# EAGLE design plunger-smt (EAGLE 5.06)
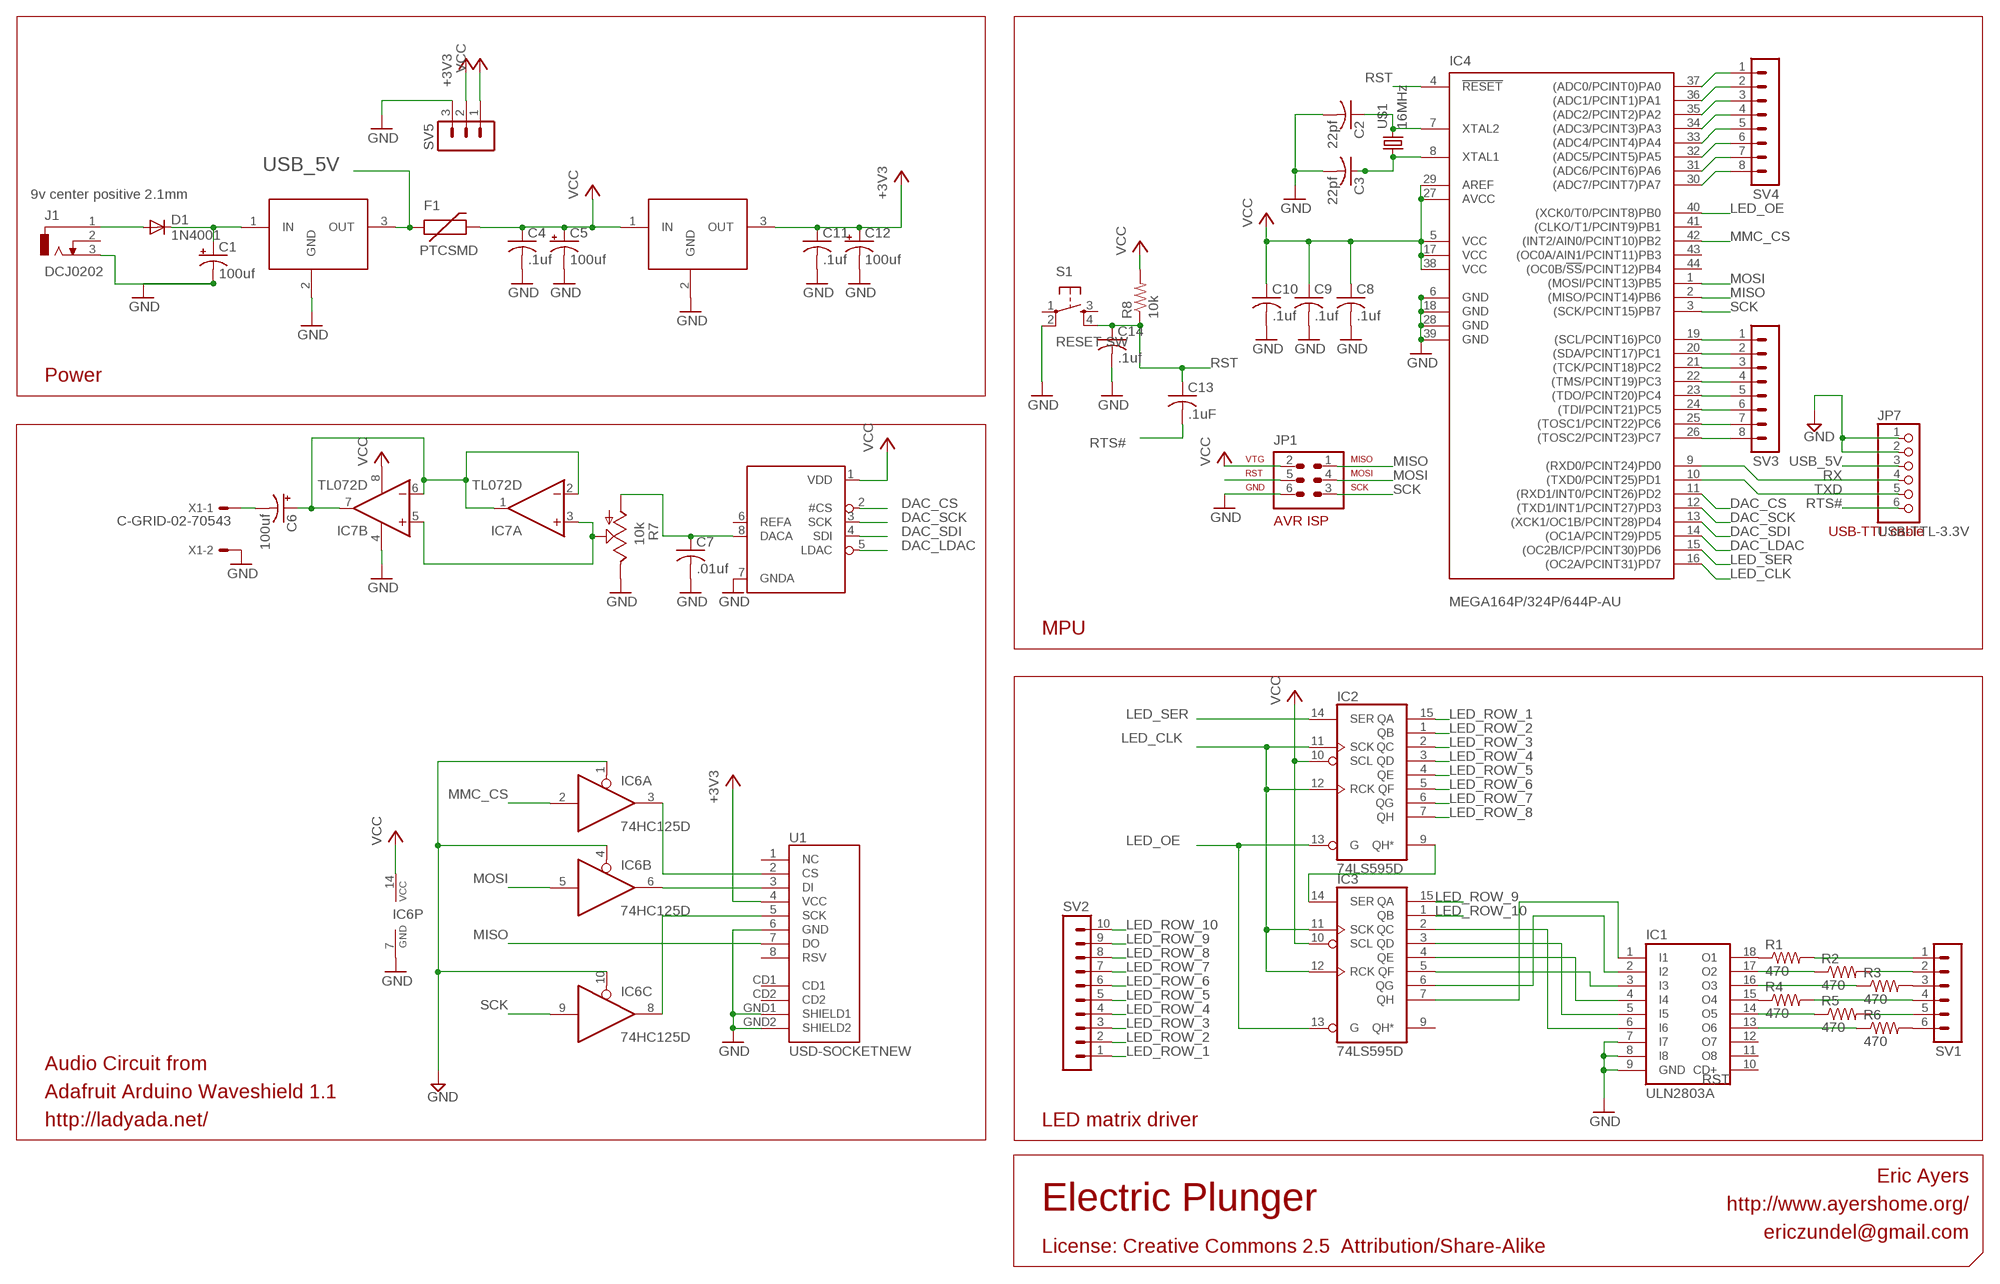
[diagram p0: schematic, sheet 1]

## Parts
C1  100uf  CPOL-USE  [PANASONIC_E]
C2  22pf  C-USC0805  [C0805]
C3  22pf  C-USC0805  [C0805]
C4  .1uf  C-USC0805  [C0805]
C5  100uf  CPOL-USE  [PANASONIC_E]
C6  100uf  CPOL-USD  [PANASONIC_D]
C7  .01uf  C-USC0805  [C0805]
C8  .1uf  C-USC0805  [C0805]
C9  .1uf  C-USC0805  [C0805]
C10  .1uf  C-USC0805  [C0805]
C11  .1uf  C-USC0805  [C0805]
C12  100uf  CPOL-USE  [PANASONIC_E]
C13  .1uF  C-USC0805  [C0805]
C14  .1uf  C-USC0805  [C0805]
D1  1N4001  DIODEPTH  [DIODE-1N4001]
F1  PTCSMD  [PTC-1206]
IC1  ULN2803A  ULN2803AULN2803ADW  [SO18W]
IC2  74LS595D  [SO16]
IC3  74LS595D  [SO16]
IC4  MEGA164P/324P/644P-AU  [TQFP44]
IC6  74HC125D  [SO14]
IC7  TL072D  [SO08]
J1  DCJ0202  [DCJ0202]
JP1  AVR-ISP-6  [AVR-ISP-6]
JP7  USB-TTL-3.3V  PINHD-1X6CLEAN  [1X06-CLEAN]
R1  470  R-US_R0805  [R0805]
R2  470  R-US_R0805  [R0805]
R3  470  R-US_R0805  [R0805]
R4  470  R-US_R0805  [R0805]
R5  470  R-US_R0805  [R0805]
R6  470  R-US_R0805  [R0805]
R7  10k  TRIM_US-S63S  [S63S]
R8  10k  R-US_R0805  [R0805@1]
REG3.3  KFBDT  [DPACK]
REG5.5  KFBDT  [DPACK]
S1  RESET SW  TAC_SWITCHPTH  [TACTILE-PTH]
SV1  MA06-1  [MA06-1]
SV2  MA10-1  [MA10-1]
SV3  MA08-1  [MA08-1]
SV4  MA08-1  [MA08-1]
SV5  MA03-1  [MA03-1]
U1  USD-SOCKETNEW  [MICRO-SD-SOCKET-PP]
U$1  16MHz  CRYTALTC26H  [TC26H]
U$2  MCP4921  [SO8]
X1  C-GRID-02-70543  [70543-02]

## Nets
+3V3: C11.1 C12.+ REG3.3.3(OUT) SV5.2 U1.4(VCC)
DAC_CS: IC4.11((RXD1/INT0/PCINT26)PD2) U$2.2(#CS)
DAC_LDAC: IC4.14((OC1A/PCINT29)PD5) U$2.5(LDAC)
DAC_SCK: IC4.12((TXD1/INT1/PCINT27)PD3) U$2.3(SCK)
DAC_SDI: IC4.13((XCK1/OC1B/PCINT28)PD4) U$2.4(SDI)
GND: C1.- C2.2 C3.2 C4.2 C5.- C7.2 C8.2 C9.2 C10.2 C11.2 C12.- C14.2 IC1.7(I7) IC1.8(I8) IC1.9(GND) IC4.6(GND) IC4.18(GND) IC4.28(GND) IC4.39(GND) IC6.1(A:OE) IC6.4(B:OE) IC6.7(P:GND) IC6.10(C:OE) IC7.4(P:V-) J1.3 JP1.6 JP7.1 JP7.2 R7.E REG3.3.2(GND) REG5.5.2(GND) S1.2 SV5.3 U1.6(GND) U1.GND1(SHIELD1) U1.GND2(SHIELD2) U$2.7(GNDA) X1.2
LED_CLK: IC2.11(SCK) IC2.12(RCK) IC3.11(SCK) IC3.12(RCK) IC4.16((OC2A/PCINT31)PD7)
LED_COL_1: R1.2 SV1.1
LED_COL_3: R3.2 SV1.3
LED_COL_4: R4.2 SV1.4
LED_COL_5: R5.2 SV1.5
LED_COL_6: R6.2 SV1.6
LED_OE: IC2.13(G) IC3.13(G) IC4.40((XCK0/T0/PCINT8)PB0)
LED_ROW_1: IC2.15(QA) SV2.1
LED_ROW_2: IC2.1(QB) SV2.2
LED_ROW_3: IC2.2(QC) SV2.3
LED_ROW_4: IC2.3(QD) SV2.4
LED_ROW_5: IC2.4(QE) SV2.5
LED_ROW_6: IC2.5(QF) SV2.6
LED_ROW_7: IC2.6(QG) SV2.7
LED_ROW_8: IC2.7(QH) SV2.8
LED_ROW_9: IC3.15(QA) SV2.9
LED_ROW_10: IC3.1(QB) SV2.10
LED_SER: IC2.14(SER) IC4.15((OC2B/ICP/PCINT30)PD6)
MISO: IC4.2((MISO/PCINT14)PB6) JP1.1 U1.7(DO)
MMC_CS: IC4.42((INT2/AIN0/PCINT10)PB2) IC6.2(A:I)
MOSI: IC4.1((MOSI/PCINT13)PB5) IC6.5(B:I) JP1.4
N$2: IC1.6(I6) IC3.2(QC)
N$3: IC1.5(I5) IC3.3(QD)
N$4: IC1.4(I4) IC3.4(QE)
N$5: IC1.3(I3) IC3.5(QF)
N$6: IC1.2(I2) IC3.6(QG)
N$8: R2.2 SV1.2
N$10: IC1.13(O6) R6.1
N$11: IC1.18(O1) R1.1
N$12: IC1.16(O3) R3.1
N$13: IC1.14(O5) R5.1
N$14: IC1.1(I1) IC3.7(QH)
N$18: IC1.15(O4) R4.1
N$20: IC1.17(O2) R2.1
N$21: IC4.37((ADC0/PCINT0)PA0) SV4.1
N$23: IC2.9(QH*) IC3.14(SER)
N$24: C2.1 IC4.7(XTAL2) U$1.2
N$25: C3.1 IC4.8(XTAL1) U$1.1
N$30: IC4.36((ADC1/PCINT1)PA1) SV4.2
N$34: C1.+ D1.C REG5.5.1(IN)
N$35: IC6.6(B:O) U1.3(DI)
N$36: IC6.3(A:O) U1.2(CS)
N$37: C6.+ IC7.1(A:OUT) IC7.2(A:-IN) IC7.6(B:-IN) IC7.7(B:OUT)
N$38: IC7.3(A:+IN) IC7.5(B:+IN) R7.S
N$39: C6.- X1.1
N$40: IC4.35((ADC2/PCINT2)PA2) SV4.3
N$41: IC6.8(C:O) U1.5(SCK)
N$42: C7.1 R7.A U$2.8(DACA)
N$43: IC4.34((ADC3/PCINT3)PA3) SV4.4
N$44: IC4.33((ADC4/PCINT4)PA4) SV4.5
N$46: IC4.32((ADC5/PCINT5)PA5) SV4.6
N$47: IC4.31((ADC6/PCINT6)PA6) SV4.7
N$48: IC4.30((ADC7/PCINT7)PA7) SV4.8
N$49: D1.A J1.1
N$51: IC4.19((SCL/PCINT16)PC0) SV3.1
N$52: IC4.20((SDA/PCINT17)PC1) SV3.2
N$53: IC4.21((TCK/PCINT18)PC2) SV3.3
N$54: IC4.22((TMS/PCINT19)PC3) SV3.4
N$55: IC4.23((TDO/PCINT20)PC4) SV3.5
N$56: IC4.24((TDI/PCINT21)PC5) SV3.6
N$57: IC4.25((TOSC1/PCINT22)PC6) SV3.7
N$58: IC4.26((TOSC2/PCINT23)PC7) SV3.8
RST: C13.1 C14.1 IC4.4(!RESET) JP1.5 R8.1 S1.4
RTS#: C13.2 JP7.6
RX: IC4.9((RXD0/PCINT24)PD0) JP7.4
SCK: IC4.3((SCK/PCINT15)PB7) IC6.9(C:I) JP1.3
TXD: IC4.10((TXD0/PCINT25)PD1) JP7.5
USB_5V: F1.1 JP7.3 REG5.5.3(OUT)
VCC: C4.1 C5.+ C8.1 C9.1 C10.1 F1.2 IC2.10(SCL) IC3.10(SCL) IC4.5(VCC) IC4.17(VCC) IC4.27(AVCC) IC4.29(AREF) IC4.38(VCC) IC6.14(P:VCC) IC7.8(P:V+) JP1.2 R8.2 REG3.3.1(IN) SV5.1 U$2.1(VDD)
Unconnected: IC1.10(CD+) IC1.11(O8) IC1.12(O7) IC3.9(QH*) IC4.41((CLKO/T1/PCINT9)PB1) IC4.43((OC0A/AIN1/PCINT11)PB3) IC4.44((OC0B/!SS!/PCINT12)PB4) IC6.11(D:O) IC6.12(D:I) IC6.13(D:OE) J1.2 S1.1 S1.3 U1.1(NC) U1.8(RSV) U1.CD1 U1.CD2 U$2.6(REFA)

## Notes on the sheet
- 9v center positive 2.1mm
- Power
- USB-TTL cable
- MPU
- Audio Circuit from
- Adafruit Arduino Waveshield 1.1
- http://ladyada.net/ | LED matrix driver
- Eric Ayers
- Electric Plunger | http://www.ayershome.org/
- ericzundel@gmail.com
- License: Creative Commons 2.5  Attribution/Share-Alike

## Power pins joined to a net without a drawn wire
GND: IC2.8(GND) IC3.8(GND)
VCC: IC2.16(VCC) IC3.16(VCC)

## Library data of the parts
C1 C5 C6 C12 = resistor:CPOL-US: POLARIZED CAPACITOR, American symbol
C2 C3 C7-C10 C13 C14 = rcl:C-US: CAPACITOR, American symbol
C4 C11 = resistor:C-US: CAPACITOR, American symbol
D1 = SparkFun:DIODE: Diode
F1 = SparkFun:PTC: Resettable Fuse PTC
IC1 = uln-udn:ULN2803A: DRIVER ARRAY
IC2 IC3 = 74xx-us:74*595: 8-bit SHIFT REGISTER, output latch
IC4 = avr-5-4.16:MEGA164P/324P/644P-AU
IC6 = 74xx-eu:74*125: Quad bus BUFFER, 3-state
IC7 = linear:TL072: OP AMP
J1 = con-jack:DCJ0202: DC POWER JACK Source: DCJ0202.pdf
JP1 = avr-5-4.16:AVR-ISP-6: AVR ISP-6 Serial Programming Header
JP7 = carduino:PINHD-1X6: PIN HEADER
R1-R6 = resistor:R-US_: RESISTOR, American symbol
R7 = pot:TRIM_US-: POTENTIOMETER
R8 = rcl:R-US_: RESISTOR, American symbol
REG3.3 REG5.5 = eza-custom:KF*BDT: LDO Voltage Regulator
S1 = SparkFun:TAC_SWITCH: Momentary Switch Button commonly used for reset or general input. Spark Fun Electronics SKU : COM-00097
SV1 = con-lstb:MA06-1: PIN HEADER
SV2 = con-lstb:MA10-1: PIN HEADER
SV3 SV4 = con-lstb:MA08-1: PIN HEADER
SV5 = con-lstb:MA03-1: PIN HEADER
U1 = SparkFun:USD-SOCKET: microSD Socket Push-push type uSD socket. Schematic element and footprint production proven. Spark Fun Electronics SKU : PRT-00127. tDoc lines correctly indicate media card edge positions when inserting (unlocked, locked, depressed).
U$1 = crystal:CRYTAL: CRYSTAL
U$2 = eza-custom:MCP4921
X1 = con-molex:C-GRID-02: CONNECTOR

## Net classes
2 gnd: width 0.305 mm, drill 0.508 mm, clearance 0.152 mm
3 usbvcc: width 0.508 mm, drill 0.508 mm, clearance 0.152 mm

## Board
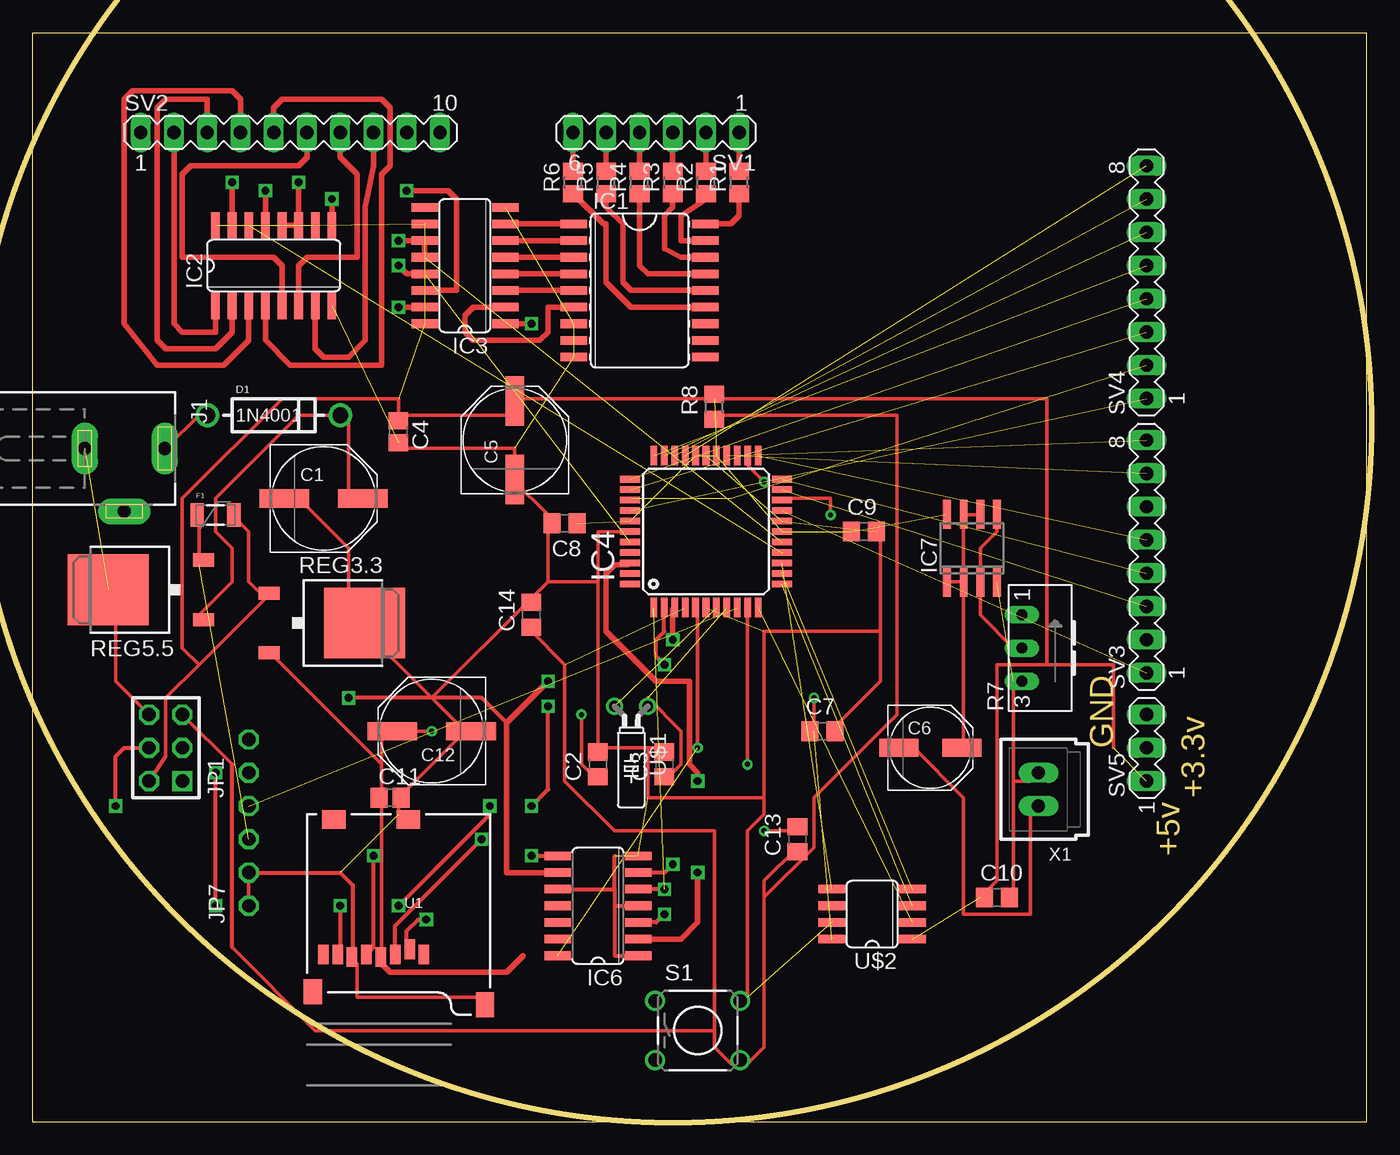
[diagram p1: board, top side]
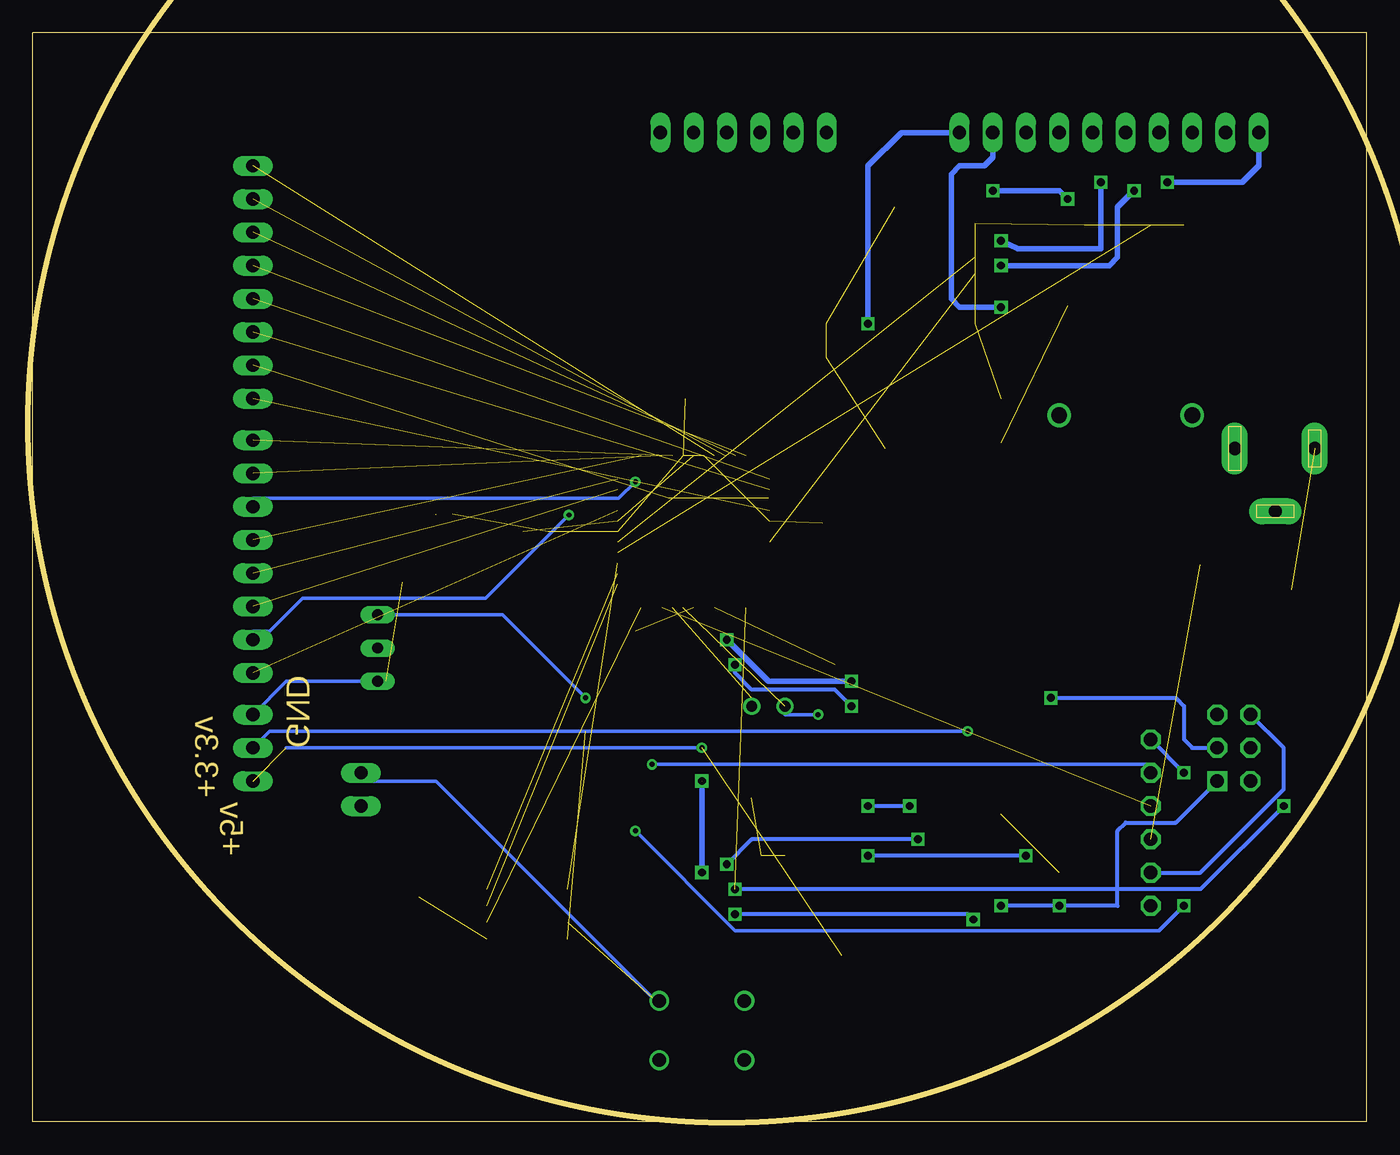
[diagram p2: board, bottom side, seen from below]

Size 101.92 x 83.19 mm. Coordinates in mm from the lower left corner, seen from the top.
Outline: 101.91,83.17 101.91,0 0,0 0,83.19 101.92,83.19
Copper layers (1*16): Top 0.035mm / dielectric 1.5mm / Bottom 0.035mm
Design rules "default *": minimum track width 10mil, minimum drill 15mil, track to track 8mil, track to pad 8mil, pad to pad 8mil, via to via 8mil, smd to smd 8mil, copper to edge 40mil, drill to drill 8mil, minimum pad ring 10mil, minimum via ring 8mil, stop-mask expansion 4mil, vias tented up to drill 0mil, thermal gap 10mil
Milling: area -4.5,0 to 102.3,106.7

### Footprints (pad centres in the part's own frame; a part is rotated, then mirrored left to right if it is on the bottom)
PANASONIC_E = smd 3.8 x 1.4: + 3,0; - -3,0
C0805 = smd 1.3 x 1.5: 1 -0.95,0; 2 0.95,0
C0805' = smd 1.3 x 1.5: 1 -0.85,0; 2 0.85,0
PANASONIC_D = smd 3 x 1.4: + 2.4,0; - -2.4,0
DIODE-1N4001 = drill 1.2 round: A -5.08,0; C 5.08,0
PTC-1206 = smd 1 x 1.8: 1 -1.4,0; 2 1.4,0
SO18W = smd 0.66 x 2.032: 1 -5.08,-5.029; 2 -3.81,-5.029; 3 -2.54,-5.029; 4 -1.27,-5.029; 5 0,-5.029; 6 1.27,-5.029; 7 2.54,-5.029; 8 3.81,-5.029; 9 5.08,-5.029; 10 5.08,5.029; 11 3.81,5.029; 12 2.54,5.029; 13 1.27,5.029; 14 0,5.029; 15 -1.27,5.029; 16 -2.54,5.029; 17 -3.81,5.029; 18 -5.08,5.029
SO16 = smd 0.66 x 2.032: 1 -4.445,-3.073; 2 -3.175,-3.073; 3 -1.905,-3.073; 4 -0.635,-3.073; 5 0.635,-3.073; 6 1.905,-3.073; 7 3.175,-3.073; 8 4.445,-3.073; 9 4.445,3.073; 10 3.175,3.073; 11 1.905,3.073; 12 0.635,3.073; 13 -0.635,3.073; 14 -1.905,3.073; 15 -3.175,3.073; 16 -4.445,3.073
TQFP44 = smd 1.5 x 0.5: 1 -5.8,4; 2 -5.8,3.2; 3 -5.8,2.4; 4 -5.8,1.6; 5 -5.8,0.8; 6 -5.8,0; 7 -5.8,-0.8; 8 -5.8,-1.6; 9 -5.8,-2.4; 10 -5.8,-3.2; 11 -5.8,-4; 23 5.8,-4; 24 5.8,-3.2; 25 5.8,-2.4; 26 5.8,-1.6; 27 5.8,-0.8; 28 5.8,0; 29 5.8,0.8; 30 5.8,1.6; 31 5.8,2.4; 32 5.8,3.2; 33 5.8,4 | smd 0.5 x 1.5: 12 -4,-5.8; 13 -3.2,-5.8; 14 -2.4,-5.8; 15 -1.6,-5.8; 16 -0.8,-5.8; 17 0,-5.8; 18 0.8,-5.8; 19 1.6,-5.8; 20 2.4,-5.8; 21 3.2,-5.8; 22 4,-5.8; 34 4,5.8; 35 3.2,5.8; 36 2.4,5.8; 37 1.6,5.8; 38 0.8,5.8; 39 0,5.8; 40 -0.8,5.8; 41 -1.6,5.8; 42 -2.4,5.8; 43 -3.2,5.8; 44 -4,5.8
SO14 = smd 0.66 x 2.032: 1 -3.81,-3.073; 2 -2.54,-3.073; 3 -1.27,-3.073; 4 0,-3.073; 5 1.27,-3.073; 6 2.54,-3.073; 7 3.81,-3.073; 8 3.81,3.073; 9 2.54,3.073; 10 1.27,3.073; 11 0,3.073; 12 -1.27,3.073; 13 -2.54,3.073; 14 -3.81,3.073
SO08 = smd 0.6 x 2.2: 1 -1.905,-2.6; 2 -0.635,-2.6; 3 0.635,-2.6; 4 1.905,-2.6; 5 1.905,2.6; 6 0.635,2.6; 7 -0.635,2.6; 8 -1.905,2.6
DCJ0202 = drill 1 pad 2 long: 1 0,3.1; 2 4.8,0; 3 0,-3
AVR-ISP-6 = drill 1.016 square: 1 -2.54,-1.27 | drill 1.016 octagon: 2 -2.54,1.27; 3 0,-1.27; 4 0,1.27; 5 2.54,-1.27; 6 2.54,1.27
1X06-CLEAN = drill 1.016 octagon: 1 -6.35,0; 2 -3.81,0; 3 -1.27,0; 4 1.27,0; 5 3.81,0; 6 6.35,0
R0805 = smd 1.3 x 1.5: 1 -0.85,0; 2 0.85,0
S63S = drill 0.813 long: A 2.54,1.27; E -2.54,1.27; S 0,1.27
R0805@1 = smd 1.3 x 1.5: 1 -0.95,0; 2 0.95,0
DPACK = smd 1 x 1.6: 1 -2.28,-4.8; 3 2.28,-4.8 | smd 5.4 x 6.2: 2 0,2.5
TACTILE-PTH = drill 1.016 round: 1 -3.251,2.261; 2 3.251,2.261; 3 -3.251,-2.261; 4 3.251,-2.261
MA06-1 = drill 1.016 long: 1 -6.35,0; 2 -3.81,0; 3 -1.27,0; 4 1.27,0; 5 3.81,0; 6 6.35,0
MA10-1 = drill 1.016 long: 1 -11.43,0; 2 -8.89,0; 3 -6.35,0; 4 -3.81,0; 5 -1.27,0; 6 1.27,0; 7 3.81,0; 8 6.35,0; 9 8.89,0; 10 11.43,0
MA08-1 = drill 1.016 long: 1 -8.89,0; 2 -6.35,0; 3 -3.81,0; 4 -1.27,0; 5 1.27,0; 6 3.81,0; 7 6.35,0; 8 8.89,0
MA03-1 = drill 1.016 long: 1 -2.54,0; 2 0,0; 3 2.54,0
MICRO-SD-SOCKET-PP = smd 0.8 x 1.5: 1 -8.94,10.7; 2 -7.84,10.3; 3 -6.74,10.7; 4 -5.64,10.9; 5 -4.54,10.7; 6 -3.44,10.9; 7 -2.34,10.7; 8 -1.24,10.7 | smd 1.4 x 1.9: CD1 -0.45,13.55; GND1 -13.6,14.55 | smd 1.8 x 1.4: CD2 -2.05,0.4; GND2 -7.75,0.4
TC26H = drill 0.813 round: 1 -1.27,0; 2 1.27,0
SO8 = smd 0.66 x 2.032: 1 -12.065,4.547; 2 -10.795,4.547; 3 -9.525,4.547; 4 -8.255,4.547; 5 -8.255,10.693; 6 -9.525,10.693; 7 -10.795,10.693; 8 -12.065,10.693
70543-02 = drill 1.016 long: 1 -1.27,0; 2 1.27,0

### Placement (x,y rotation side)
C1  22.23,47.62 0 top
C2  43.18,27.3 90 top
C3  48.26,27.3 90 top
C4  .1uf  [C0805']  27.94,52.7 270 top
C5  36.83,52.07 90 top
C6  68.58,28.57 0 top
C7  60.33,29.84 0 top
C8  40.64,45.72 180 top
C9  63.5,45.09 0 top
C10  73.66,17.14 0 top
C11  .1uf  [C0805']  27.3,24.77 0 top
C12  30.48,29.84 180 top
C13  58.42,21.59 90 top
C14  38.1,38.73 90 top
D1  18.41,53.98 0 top
F1  13.97,46.35 0 top
IC1  46.35,63.5 270 top
IC2  18.41,65.41 0 top
IC3  33.02,65.41 90 top
IC4  51.44,45.09 90 top
IC6  43.18,16.51 90 top
IC7  71.75,43.81 0 top
J1  6.99,51.44 270 top
JP1  10.16,28.57 90 top
JP7  16.51,22.86 90 top
R1  53.98,71.75 90 top
R2  51.44,71.75 90 top
R3  48.9,71.75 90 top
R4  46.35,71.75 90 top
R5  43.81,71.75 90 top
R6  41.27,71.75 90 top
R7  76.83,36.2 90 top
R8  52.07,54.61 90 top
REG3.3  22.86,38.1 270 top
REG5.5  8.26,40.64 90 top
S1  50.8,6.99 0 top
SV1  47.62,75.56 180 top
SV2  19.68,75.56 0 top
SV3  85.09,43.18 90 top
SV4  85.09,64.14 90 top
SV5  85.09,28.57 90 top
U1  20.95,23.5 180 top
U$1  45.72,31.75 180 top
U$2  71.75,26.04 90 top
X1  76.83,25.4 90 top

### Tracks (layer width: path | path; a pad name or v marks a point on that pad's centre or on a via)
+3V3  (via drill 0.38)
  Top 0.254: 26.67,27.3 26.67,29.84 C12.+ v30.48,29.84 | 26.67,24.77 26.67,27.3 | 26.67,24.77 26.67,13.34 U1.4 | 26.67,24.77 C11.1 | 26.67,27.3 17.78,36.2 REG3.3.3
  Top 0.406: 37.47,12.7 36.2,11.43 27.3,11.43 26.67,12.06 26.67,12.52 U1.4
  Bottom 0.254: SV5.2 83.82,29.84 v30.48,29.84
DAC_CS  (1 unrouted)
DAC_LDAC  (1 unrouted)
DAC_SCK  (1 unrouted)
DAC_SDI  (1 unrouted)
GND  (14 unrouted)
  Top 0.254: 46.99,28.57 48.26,28.57 C3.2 | 43.18,28.57 46.99,28.57 | 43.18,41.27 43.18,28.57 | 43.18,41.27 43.18,45.09 IC4.39 45.72,45.09 | 43.18,28.57 C2.2 | 38.1,40.01 39.37,41.27 | 39.37,41.27 39.37,45.09 C8.2 39.37,46.35 36.83,48.9 C5.- 36.83,51.44 27.94,51.44 C4.2 | 39.37,41.27 43.18,41.27 | U1.6 24.77,12.06 24.77,9.53 34.29,9.53 U1.GND1 | 27.94,24.77 27.94,23.5 U1.GND2 | 27.94,24.77 33.02,29.84 | C11.2 27.94,24.77 | C1.- 20.32,47.62 24.13,43.81 24.13,38.73 REG3.3.2 25.4,37.47 30.48,32.38 | 33.02,29.84 30.48,32.38 | 33.02,29.84 C12.- | 30.48,32.38 38.1,40.01 | 38.1,40.01 C14.2 | JP1.6 6.35,33.66 6.35,40.01 REG5.5.2 | 74.93,26.04 74.93,33.66 R7.E | 74.93,26.04 74.93,17.14 C10.2 | 64.77,37.47 64.77,45.09 C9.2 | 64.77,37.47 64.77,33.66 60.96,29.84 C7.2 | 64.77,37.47 55.88,37.47 55.88,24.77 | 55.88,24.77 55.88,23.5 54.61,22.23 54.61,9.53 S1.2 | 74.93,26.04 76.2,26.04 X1.2 | 46.99,28.57 46.99,24.77 55.88,24.77 | JP7.1 JP7.2 JP7.1
  Top 0.305: 44.45,17.78 44.45,20.32 | 44.45,17.78 44.45,16.51 | IC6.10 44.45,17.78 | 44.45,16.51 IC6.4 | 44.45,16.51 44.45,12.7 IC6.1 | JP7.2 23.5,19.05 24.45,18.1 24.45,12.65 U1.6
  Bottom 0.254: SV5.3 82.55,33.66 R7.E | S1.2 54.61,9.53 71.12,26.04 76.2,26.04 X1.2
  Bottom 0.305: JP1.6 6.35,28.57 6.35,25.4 12.7,19.05 JP7.2
LED_CLK  (via drill 0.6)  (1 unrouted)
  Top 0.406: IC3.12 IC3.11 v27.94,67.31 | v20.32,71.75 IC2.11 IC2.12
  Bottom 0.406: v27.94,67.31 26.67,66.67 20.32,66.67 v20.32,71.75
LED_COL_1
  Top 0.406: R1.2 SV1.1
LED_COL_3
  Top 0.406: R3.2 SV1.3
LED_COL_4
  Top 0.406: R4.2 SV1.4
LED_COL_5
  Top 0.406: R5.2 SV1.5
LED_COL_6
  Top 0.406: R6.2 SV1.6
LED_OE  (via drill 0.6)  (1 unrouted)
  Top 0.406: IC3.13 28.57,64.77 v27.94,65.41 | v17.78,71.12 IC2.13
  Bottom 0.406: v27.94,65.41 19.68,65.41 19.05,66.04 19.05,69.85 v17.78,71.12
LED_ROW_1  (via drill 0.6)
  Top 0.406: v15.24,71.75 IC2.15
  Bottom 0.406: v15.24,71.75 9.53,71.75 8.26,73.03 SV2.1
LED_ROW_2
  Top 0.406: IC2.1 13.97,60.33 11.43,60.33 10.79,60.96 SV2.2
LED_ROW_3
  Top 0.406: IC2.2 15.24,60.33 13.97,59.05 10.16,59.05 9.53,59.69 9.53,77.47 10.16,78.11 13.34,78.11 SV2.3
LED_ROW_4
  Top 0.406: IC2.3 16.51,59.69 14.61,57.78 9.53,57.78 6.99,60.96 6.99,78.11 7.62,78.74 15.24,78.74 15.88,78.11 SV2.4
LED_ROW_5
  Top 0.406: IC2.4 17.78,59.69 19.68,57.78 26.67,57.78 26.67,72.39 27.3,73.03 27.3,77.47 26.67,78.11 19.05,78.11 18.41,77.47 SV2.5
LED_ROW_6
  Top 0.406: IC2.5 19.05,65.41 18.41,66.04 11.43,66.04 11.43,72.39 12.06,73.03 20.32,73.03 20.95,73.66 SV2.6
LED_ROW_7
  Top 0.406: IC2.6 20.32,65.41 20.95,66.04 24.77,66.04 24.77,72.39 23.5,73.66 SV2.7
LED_ROW_8
  Top 0.406: SV2.8 26.04,73.03 25.4,69.85 25.4,59.69 24.13,58.42 22.23,58.42 21.59,59.05 IC2.7
LED_ROW_9  (via drill 0.6)
  Top 0.406: IC3.15 v27.94,62.23
  Bottom 0.406: SV2.9 28.57,73.66 29.21,73.03 31.11,73.03 31.75,72.39 31.75,62.87 31.11,62.23 v27.94,62.23
LED_ROW_10  (via drill 0.6)
  Top 0.406: IC3.1 v38.1,60.96
  Bottom 0.406: v38.1,60.96 38.1,73.03 35.56,75.56 SV2.10
LED_SER  (1 unrouted)
MISO  (via drill 0.6)
  Top 0.305: U1.7 23.5,12.99 v23.5,16.51 | v27.94,16.51 34.92,23.5 v34.92,24.13 | v38.1,24.13 39.37,25.4 v39.37,31.75 | v48.26,34.92 47.62,35.56 47.62,36.83 48.23,37.44 IC4.2
  Bottom 0.305: v27.94,16.51 v23.5,16.51 19.05,16.51 19.05,22.23 18.41,22.86 14.61,22.86 JP1.1 | v34.92,24.13 v38.1,24.13 | v39.37,31.75 40.64,33.02 46.99,33.02 48.26,34.29 v48.26,34.92
MMC_CS  (via drill 0.6)  (1 unrouted)
  Top 0.406: IC6.2 49.53,13.97 50.8,15.24 v50.8,19.05 | v50.8,26.04 50.8,26.67 50.16,27.3 50.16,33.66 47.62,33.66 43.81,37.47 43.81,41.91 44.45,42.55 45.49,42.55 IC4.42
  Bottom 0.406: v50.8,19.05 v50.8,26.04
MOSI  (via drill 0.6)  (1 unrouted)
  Top 0.305: JP1.4 6.99,28.57 6.35,27.94 v6.35,24.13 | v48.26,17.78 IC6.5
  Bottom 0.305: v6.35,24.13 12.7,17.78 v48.26,17.78
N$2
  Top 0.406: IC1.6 39.37,62.23 39.37,60.33 38.73,59.69 33.66,59.69 33.02,60.33 33.02,61.59 33.66,62.23 IC3.2
N$3
  Top 0.406: IC3.3 IC1.5
N$4
  Top 0.406: IC3.4 IC1.4
N$5
  Top 0.406: IC3.5 IC1.3
N$6
  Top 0.406: IC3.6 IC1.2
N$8
  Top 0.406: R2.2 SV1.2
N$10
  Top 0.406: IC1.13 45.72,62.23 43.81,64.14 43.81,68.58 43.6,68.58 R6.1
N$11
  Top 0.406: R1.1 53.98,69.22 53.34,68.58 IC1.18
N$12
  Top 0.406: R3.1 48.9,69.85 48.26,69.22 48.26,66.67 49.53,66.04 IC1.16
N$13
  Top 0.406: R5.1 43.81,69.85 45.09,68.58 45.09,64.14 45.72,63.5 IC1.14
N$14
  Top 0.406: IC3.7 IC1.1
N$18
  Top 0.406: IC1.15 46.99,64.77 46.35,65.41 R4.1
N$20
  Top 0.406: R2.1 51.44,70.48 49.53,69.22 49.53,67.31 IC1.17
N$21  (1 unrouted)
N$23  (via drill 0.6)
  Top 0.406: IC3.14 32.38,63.5 32.38,70.48 31.75,71.12 v28.57,71.12 | IC2.9 v22.86,70.48
  Bottom 0.406: v28.57,71.12 23.5,71.12 v22.86,70.48
N$24  (via drill 0.38)  (1 unrouted)
  Top 0.254: v41.91,31.11 41.91,27.3 43.18,26.04 C2.1
  Bottom 0.254: v41.91,31.11 44.45,31.11 U$1.2
N$25  (1 unrouted)
  Top 0.254: C3.1 48.26,26.04 49.53,27.3 49.53,29.84 46.99,32.38 U$1.1
N$30  (3 unrouted)
  Top 0.254: IC4.36 45.72,47.62
N$34
  Top 0.254: REG5.5.1 12.7,38.73 15.24,41.27 15.24,43.81 13.97,45.09 13.97,47.62 20.32,53.98 D1.C 24.13,53.98 24.13,47.62 C1.+
N$35  (via drill 0.6)
  Top 0.305: U1.3 27.7,14.99 v34.29,21.59 | v48.9,19.68 48.26,19.05 IC6.6
  Bottom 0.305: v34.29,21.59 46.99,21.59 v48.9,19.68
N$36  (via drill 0.6)
  Top 0.305: U1.2 28.57,13.34 28.57,14.61 29.43,15.46 v30.07,15.46 | IC6.3 47.62,15.24 v48.26,15.88
  Bottom 0.305: v48.26,15.88 30.48,15.88 v30.07,15.46
N$37  (1 unrouted)
  Top 0.254: 71.12,41.27 69.85,41.27 IC7.1 | IC7.6 72.39,46.35 71.12,46.35 71.12,41.27 | C6.+ 71.12,28.57 IC7.2 71.12,41.27
N$38
  Top 0.254: IC7.5 73.66,45.09 72.39,43.81 IC7.3 72.39,38.73 74.93,36.2 R7.S
N$39
  Top 0.254: C6.- 67.31,28.57 71.12,24.77 71.12,15.88 76.2,15.88 76.2,23.5 X1.1
N$40  (1 unrouted)
N$41  (via drill 0.6)
  Top 0.305: U1.5 26.04,13.34 v26.04,20.32 | v38.1,20.32 IC6.8
  Bottom 0.305: v26.04,20.32 v38.1,20.32
N$42  (via drill 0.38)  (1 unrouted)
  Top 0.254: v59.69,32.38 59.69,29.84 C7.1
  Bottom 0.254: v59.69,32.38 66.04,38.73 R7.A
N$43  (1 unrouted)
N$44  (1 unrouted)
N$46  (1 unrouted)
N$47  (1 unrouted)
N$48  (1 unrouted)
N$49
  Top 0.254: D1.A 12.7,53.98 10.16,51.44 J1.1
N$51  (1 unrouted)
N$52  (via drill 0.38)
  Top 0.254: v60.96,46.35 60.96,47.62 57.15,47.62 IC4.20
  Bottom 0.254: v60.96,46.35 67.31,40.01 81.28,40.01 83.82,37.47 85.09,37.47 SV3.2
N$53  (1 unrouted)
N$54  (1 unrouted)
N$55  (1 unrouted)
N$56  (via drill 0.38)
  Top 0.254: v55.88,48.9 54.61,50.16 IC4.24
  Bottom 0.254: v55.88,48.9 57.15,47.62 85.09,47.62 SV3.6
N$57  (1 unrouted)
N$58  (1 unrouted)
RST  (1 unrouted)
  Top 0.254: 55.88,17.14 55.88,5.71 54.61,4.45 S1.4 53.34,4.45 52.07,5.71 52.07,6.99 | 55.88,17.14 55.88,18.41 58.42,20.95 C13.1 | 52.07,6.99 52.07,22.23 44.45,22.23 40.64,26.04 40.64,34.92 38.1,37.47 C14.1 | 55.88,17.14 59.69,20.95 59.69,24.77 66.04,31.11 66.04,53.98 52.07,53.98 R8.1 | JP1.5 15.24,27.3 | 15.24,13.34 21.59,6.99 52.07,6.99
  Top 0.305: 15.24,13.34 15.24,27.3
RTS#  (via drill 0.38, 0.6)
  Top 0.254: v55.88,22.23 58.42,22.23 C13.2
  Top 0.305: v13.97,16.51 v13.97,26.67
  Bottom 0.254: v55.88,22.23 48.26,14.61 15.88,14.61
  Bottom 0.305: 15.88,14.61 v13.97,16.51 | v13.97,26.67 JP7.6
RX  (1 unrouted)
SCK  (via drill 0.6)
  Top 0.305: 36.2,30.48 34.29,32.38 v24.13,32.38
  Top 0.406: IC6.9 36.2,19.05 36.2,30.48 v39.37,33.66 | v48.9,36.83 48.9,39.15 IC4.3
  Bottom 0.305: v24.13,32.38 14.61,32.38 13.97,31.75 13.97,29.21 13.34,28.57 JP1.3
  Bottom 0.406: v39.37,33.66 45.72,33.66 v48.9,36.83
TXD  (via drill 0.38)
  Top 0.254: v54.61,27.3 54.61,38.73 IC4.10
  Bottom 0.254: v54.61,27.3 16.51,27.3 JP7.5
USB_5V  (1 unrouted)
  Top 0.254: REG5.5.3 12.7,42.55 12.7,46.35 F1.1
VCC  (via drill 0.38)  (15 unrouted)
  Top 0.254: 17.78,40.01 16.51,41.27 16.51,45.09 15.24,46.35 F1.2 | JP1.2 10.16,27.94 10.16,32.38 12.7,34.92 | 12.7,34.92 17.78,40.01 | 17.78,40.01 REG3.3.1 | 27.94,53.98 36.83,53.98 C5.+ 36.83,55.24 52.07,55.24 | v50.8,28.57 50.8,38.73 IC4.5 | 77.47,34.92 82.55,34.92 82.55,28.57 | 77.47,34.92 73.66,34.92 73.66,18.41 72.39,17.14 C10.1 | 52.07,55.24 77.47,55.24 77.47,34.92 | 52.07,55.24 R8.2 | 12.7,34.92 11.43,36.2 11.43,47.62 19.05,55.24 27.94,55.24 27.94,53.98 | 27.94,53.98 C4.1
  Bottom 0.254: v50.8,28.57 82.55,28.57

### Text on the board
Milling: GND | +3.3v | +5v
